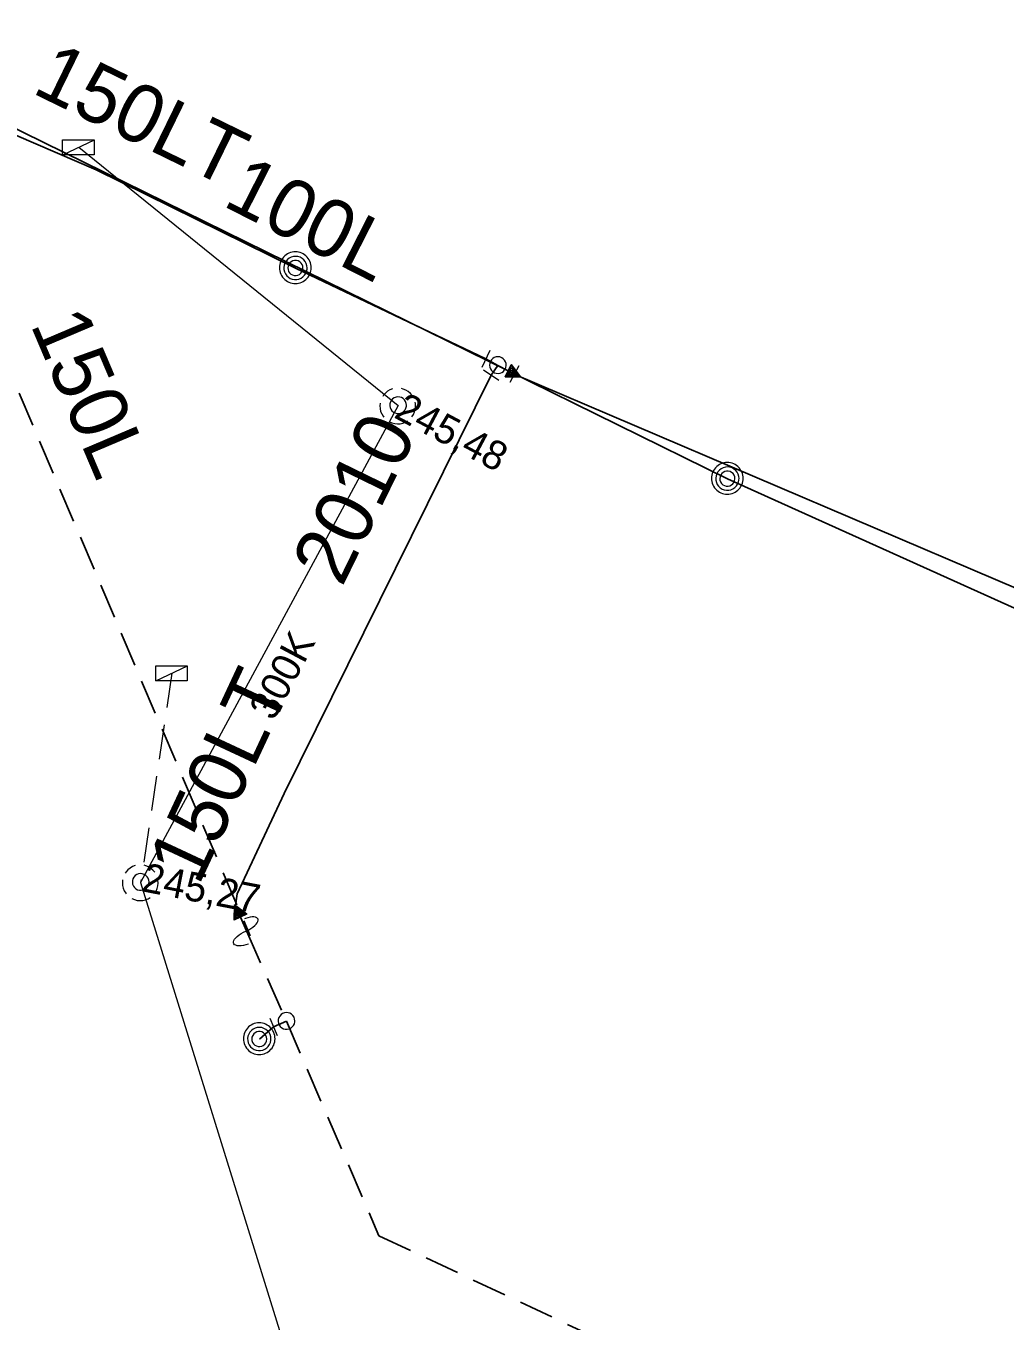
# Model space of a CAD drawing. Extents: x -735085 to -733500, y -1044153 to -1043402.
# Drawn here: x -734812.09 to -734785.04, y -1043558.45 to -1043522.67 of the extents above; entities that cross this region are included whole.
import ezdxf

# ---------------------------------------------------------------- set-up
doc = ezdxf.new("R2010")
doc.units = 0
doc.header["$LTSCALE"] = 0.32
doc.linetypes.add('MEDIUM_DASHED', pattern=[4.5, 3, -1.5])
doc.layers.add('15', color=7, linetype='Continuous')
doc.layers.add('16', color=7, linetype='Continuous')
for name, color, linetype, lineweight in [('18', 7, 'Continuous', 13), ('20', 7, 'Continuous', 13), ('49', 7, 'Continuous', 13), ('8', 7, 'Continuous', 13)]:
    doc.layers.add(name, color=color, linetype=linetype, lineweight=lineweight)

msp = doc.modelspace()

# ---------------------------------------------------------------- linework, layer by layer
at = {"layer": '18'}
for p, q in [((-734811.071, -1043526.23), (-734810.196, -1043525.818)), ((-734808.501, -1043540.76), (-734807.627, -1043540.348))]:
    msp.add_line(p, q, dxfattribs=at)
for points in [[(-734811.075, -1043525.818), (-734810.201, -1043525.818), (-734810.201, -1043526.23), (-734811.075, -1043526.23)], [(-734801.578, -1043533.149), (-734801.584, -1043533.097), (-734801.602, -1043533.047), (-734801.63, -1043533.003), (-734801.668, -1043532.966), (-734801.713, -1043532.939), (-734801.763, -1043532.923), (-734801.815, -1043532.918), (-734801.867, -1043532.925), (-734801.916, -1043532.944), (-734801.96, -1043532.974), (-734801.995, -1043533.013), (-734802.021, -1043533.058), (-734802.036, -1043533.109), (-734802.039, -1043533.161), (-734802.031, -1043533.213), (-734802.01, -1043533.261), (-734801.98, -1043533.304), (-734801.94, -1043533.339), (-734801.894, -1043533.363), (-734801.843, -1043533.377), (-734801.791, -1043533.379), (-734801.739, -1043533.369), (-734801.691, -1043533.347), (-734801.649, -1043533.315), (-734801.616, -1043533.275), (-734801.592, -1043533.228), (-734801.58, -1043533.177)], [(-734808.505, -1043540.348), (-734807.631, -1043540.348), (-734807.631, -1043540.76), (-734808.505, -1043540.76)], [(-734808.689, -1043546.319), (-734808.695, -1043546.267), (-734808.713, -1043546.217), (-734808.741, -1043546.173), (-734808.779, -1043546.136), (-734808.824, -1043546.109), (-734808.874, -1043546.093), (-734808.926, -1043546.088), (-734808.978, -1043546.095), (-734809.027, -1043546.114), (-734809.071, -1043546.144), (-734809.106, -1043546.183), (-734809.132, -1043546.228), (-734809.147, -1043546.279), (-734809.15, -1043546.331), (-734809.142, -1043546.383), (-734809.121, -1043546.431), (-734809.091, -1043546.474), (-734809.051, -1043546.509), (-734809.005, -1043546.533), (-734808.954, -1043546.547), (-734808.902, -1043546.549), (-734808.85, -1043546.539), (-734808.802, -1043546.517), (-734808.76, -1043546.485), (-734808.727, -1043546.445), (-734808.703, -1043546.398), (-734808.691, -1043546.347)]]:
    msp.add_lwpolyline(points, close=True, dxfattribs=at)
for points in [[(-734801.962, -1043532.697), (-734802.033, -1043532.725), (-734802.1, -1043532.764), (-734802.16, -1043532.812), (-734802.211, -1043532.869), (-734802.235, -1043532.903)], [(-734801.421, -1043532.88), (-734801.471, -1043532.822), (-734801.529, -1043532.772), (-734801.594, -1043532.731), (-734801.665, -1043532.702), (-734801.714, -1043532.688)], [(-734802.307, -1043533.089), (-734802.313, -1043533.166), (-734802.308, -1043533.243), (-734802.291, -1043533.318), (-734802.262, -1043533.389), (-734802.222, -1043533.455), (-734802.206, -1043533.477)], [(-734801.426, -1043533.466), (-734801.385, -1043533.401), (-734801.354, -1043533.331), (-734801.335, -1043533.256), (-734801.327, -1043533.18), (-734801.332, -1043533.103), (-734801.338, -1043533.068)], [(-734802.049, -1043533.606), (-734801.979, -1043533.637), (-734801.904, -1043533.656), (-734801.828, -1043533.663), (-734801.751, -1043533.658), (-734801.676, -1043533.641), (-734801.604, -1043533.613), (-734801.544, -1043533.578)], [(-734809.073, -1043545.867), (-734809.144, -1043545.895), (-734809.211, -1043545.934), (-734809.271, -1043545.982), (-734809.322, -1043546.039), (-734809.346, -1043546.073)], [(-734808.532, -1043546.05), (-734808.582, -1043545.992), (-734808.64, -1043545.942), (-734808.705, -1043545.901), (-734808.776, -1043545.872), (-734808.825, -1043545.858)], [(-734809.418, -1043546.259), (-734809.424, -1043546.336), (-734809.419, -1043546.413), (-734809.402, -1043546.488), (-734809.373, -1043546.559), (-734809.333, -1043546.625), (-734809.317, -1043546.647)], [(-734808.537, -1043546.636), (-734808.496, -1043546.571), (-734808.465, -1043546.501), (-734808.446, -1043546.426), (-734808.438, -1043546.35), (-734808.443, -1043546.273), (-734808.449, -1043546.238)], [(-734809.16, -1043546.776), (-734809.09, -1043546.807), (-734809.015, -1043546.826), (-734808.939, -1043546.833), (-734808.862, -1043546.828), (-734808.787, -1043546.811), (-734808.715, -1043546.783), (-734808.655, -1043546.748)]]:
    msp.add_lwpolyline(points, dxfattribs=at)
at = {"layer": '20'}
for p, q in [((-734801.809, -1043533.16), (-734808.92, -1043546.33)), ((-734801.809, -1043533.16), (-734808.92, -1043546.33)), ((-734808.92, -1043546.33), (-734802, -1043568.65)), ((-734808.92, -1043546.33), (-734802, -1043568.65))]:
    msp.add_line(p, q, dxfattribs=at)
at = {"layer": '49'}
msp.add_line((-734810.629, -1043526.02), (-734801.809, -1043533.16), dxfattribs=at)
msp.add_line((-734810.629, -1043526.02), (-734801.809, -1043533.16), dxfattribs=at)
at = {"layer": '49', "linetype": 'MEDIUM_DASHED'}
msp.add_line((-734808.059, -1043540.55), (-734808.92, -1043546.33), dxfattribs=at)
msp.add_line((-734808.059, -1043540.55), (-734808.92, -1043546.33), dxfattribs=at)
at = {"layer": '8', "linetype": 'MEDIUM_DASHED', "lineweight": 25}
for p, q in [((-734815.66, -1043524.87), (-734805.897, -1043547.809)), ((-734806, -1043547.67), (-734804.892, -1043550.168))]:
    msp.add_line(p, q, dxfattribs=at)
at = {"layer": '8'}
for p, q in [((-734799.278, -1043531.635), (-734799.501, -1043532.102)), ((-734799.023, -1043532.463), (-734799.453, -1043532.177)), ((-734798.478, -1043532.06), (-734798.72, -1043532.517)), ((-734805.351, -1043550.08), (-734805.149, -1043550.555))]:
    msp.add_line(p, q, dxfattribs=at)
at = {"layer": '8', "lineweight": 25}
for p, q in [((-734805.25, -1043550.32), (-734805.64, -1043550.66)), ((-734804.892, -1043550.168), (-734805.25, -1043550.32))]:
    msp.add_line(p, q, dxfattribs=at)
for points in [[(-734815.949, -1043522.67), (-734815.649, -1043523.18), (-734813.73, -1043525.08), (-734813.489, -1043525.21), (-734810.149, -1043526.65), (-734804.64, -1043529.36)], [(-734814.717, -1043524.389), (-734813.287, -1043525.06), (-734798.77, -1043532.2), (-734792.71, -1043535.18)], [(-734804.64, -1043529.36), (-734799.39, -1043531.87), (-734799.059, -1043532.05), (-734799.239, -1043532.32)], [(-734799.059, -1043532.05), (-734798.77, -1043532.2), (-734798.6, -1043532.29)], [(-734799.239, -1043532.32), (-734804.96, -1043543.87), (-734806.25, -1043546.65), (-734806.3, -1043546.98), (-734806.16, -1043547.29), (-734806, -1043547.67)], [(-734798.6, -1043532.29), (-734781.989, -1043539.38), (-734773.37, -1043543.03), (-734767.76, -1043545.41), (-734738.719, -1043557.66), (-734737.059, -1043558.35)], [(-734792.71, -1043535.18), (-734782.352, -1043539.852), (-734773.644, -1043543.536), (-734767.807, -1043545.587), (-734738.734, -1043557.836), (-734732.528, -1043560.258), (-734709.46, -1043569.477), (-734674.151, -1043584.087)]]:
    msp.add_lwpolyline(points, dxfattribs=at)
at = {"layer": '8'}
for points in [[(-734804.21, -1043529.349), (-734804.212, -1043529.304), (-734804.219, -1043529.259), (-734804.231, -1043529.214), (-734804.247, -1043529.172), (-734804.268, -1043529.131), (-734804.293, -1043529.092), (-734804.322, -1043529.057), (-734804.354, -1043529.024), (-734804.39, -1043528.996), (-734804.428, -1043528.971), (-734804.469, -1043528.95), (-734804.512, -1043528.933), (-734804.556, -1043528.921), (-734804.601, -1043528.914), (-734804.647, -1043528.912), (-734804.693, -1043528.914), (-734804.738, -1043528.921), (-734804.782, -1043528.933), (-734804.825, -1043528.95), (-734804.866, -1043528.971), (-734804.904, -1043528.996), (-734804.94, -1043529.024), (-734804.972, -1043529.057), (-734805.001, -1043529.092), (-734805.026, -1043529.131), (-734805.047, -1043529.172), (-734805.063, -1043529.214), (-734805.075, -1043529.259), (-734805.082, -1043529.304), (-734805.085, -1043529.35), (-734805.082, -1043529.395), (-734805.075, -1043529.44), (-734805.063, -1043529.485), (-734805.047, -1043529.527), (-734805.026, -1043529.568), (-734805.001, -1043529.607), (-734804.972, -1043529.642), (-734804.94, -1043529.675), (-734804.904, -1043529.703), (-734804.866, -1043529.728), (-734804.825, -1043529.749), (-734804.782, -1043529.766), (-734804.738, -1043529.777), (-734804.693, -1043529.785), (-734804.647, -1043529.787), (-734804.601, -1043529.785), (-734804.556, -1043529.777), (-734804.512, -1043529.766), (-734804.469, -1043529.749), (-734804.428, -1043529.728), (-734804.39, -1043529.703), (-734804.354, -1043529.675), (-734804.322, -1043529.642), (-734804.293, -1043529.607), (-734804.268, -1043529.568), (-734804.247, -1043529.527), (-734804.231, -1043529.485), (-734804.219, -1043529.44), (-734804.212, -1043529.395), (-734804.21, -1043529.35)], [(-734798.853, -1043532.367), (-734798.424, -1043532.364), (-734798.684, -1043532.023)], [(-734792.279, -1043535.168), (-734792.282, -1043535.123), (-734792.289, -1043535.078), (-734792.301, -1043535.033), (-734792.316, -1043534.991), (-734792.338, -1043534.95), (-734792.363, -1043534.911), (-734792.392, -1043534.876), (-734792.424, -1043534.843), (-734792.46, -1043534.815), (-734792.497, -1043534.79), (-734792.539, -1043534.769), (-734792.581, -1043534.752), (-734792.625, -1043534.74), (-734792.671, -1043534.733), (-734792.717, -1043534.731), (-734792.762, -1043534.733), (-734792.808, -1043534.74), (-734792.852, -1043534.752), (-734792.895, -1043534.769), (-734792.936, -1043534.79), (-734792.973, -1043534.815), (-734793.01, -1043534.843), (-734793.042, -1043534.876), (-734793.071, -1043534.911), (-734793.096, -1043534.95), (-734793.117, -1043534.991), (-734793.132, -1043535.033), (-734793.145, -1043535.078), (-734793.152, -1043535.123), (-734793.154, -1043535.169), (-734793.152, -1043535.214), (-734793.145, -1043535.259), (-734793.132, -1043535.304), (-734793.117, -1043535.346), (-734793.096, -1043535.387), (-734793.071, -1043535.426), (-734793.042, -1043535.461), (-734793.01, -1043535.494), (-734792.973, -1043535.522), (-734792.936, -1043535.547), (-734792.895, -1043535.568), (-734792.852, -1043535.585), (-734792.808, -1043535.596), (-734792.762, -1043535.604), (-734792.717, -1043535.606), (-734792.671, -1043535.604), (-734792.625, -1043535.596), (-734792.581, -1043535.585), (-734792.539, -1043535.568), (-734792.497, -1043535.547), (-734792.46, -1043535.522), (-734792.424, -1043535.494), (-734792.392, -1043535.461), (-734792.363, -1043535.426), (-734792.338, -1043535.387), (-734792.316, -1043535.346), (-734792.301, -1043535.304), (-734792.289, -1043535.259), (-734792.282, -1043535.214), (-734792.279, -1043535.169)], [(-734805.991, -1043547.208), (-734806.332, -1043546.948), (-734806.335, -1043547.377)], [(-734805.997, -1043547.668), (-734805.934, -1043547.637), (-734805.874, -1043547.602), (-734805.82, -1043547.563), (-734805.771, -1043547.525), (-734805.733, -1043547.486), (-734805.703, -1043547.447), (-734805.684, -1043547.41), (-734805.674, -1043547.378), (-734805.677, -1043547.348), (-734805.691, -1043547.324), (-734805.714, -1043547.305), (-734805.748, -1043547.292), (-734805.79, -1043547.286), (-734805.842, -1043547.286), (-734805.898, -1043547.292), (-734805.96, -1043547.305), (-734806.025, -1043547.324), (-734806.053, -1043547.335)], [(-734805.945, -1043548.037), (-734806.015, -1043548.058), (-734806.082, -1043548.072), (-734806.145, -1043548.081), (-734806.202, -1043548.082), (-734806.252, -1043548.078), (-734806.294, -1043548.068), (-734806.326, -1043548.052), (-734806.348, -1043548.03), (-734806.359, -1043548.003), (-734806.359, -1043547.971), (-734806.348, -1043547.936), (-734806.326, -1043547.899), (-734806.293, -1043547.86), (-734806.251, -1043547.821), (-734806.201, -1043547.782), (-734806.144, -1043547.743), (-734806.08, -1043547.709), (-734806.014, -1043547.676), (-734805.994, -1043547.668)], [(-734805.208, -1043550.648), (-734805.211, -1043550.603), (-734805.218, -1043550.558), (-734805.23, -1043550.513), (-734805.245, -1043550.471), (-734805.267, -1043550.43), (-734805.292, -1043550.391), (-734805.321, -1043550.356), (-734805.353, -1043550.323), (-734805.389, -1043550.295), (-734805.426, -1043550.27), (-734805.468, -1043550.249), (-734805.511, -1043550.232), (-734805.554, -1043550.22), (-734805.6, -1043550.213), (-734805.646, -1043550.211), (-734805.691, -1043550.213), (-734805.737, -1043550.22), (-734805.781, -1043550.232), (-734805.824, -1043550.249), (-734805.865, -1043550.27), (-734805.902, -1043550.295), (-734805.939, -1043550.323), (-734805.971, -1043550.356), (-734806, -1043550.391), (-734806.025, -1043550.43), (-734806.046, -1043550.471), (-734806.061, -1043550.513), (-734806.074, -1043550.558), (-734806.081, -1043550.603), (-734806.083, -1043550.649), (-734806.081, -1043550.694), (-734806.074, -1043550.739), (-734806.061, -1043550.784), (-734806.046, -1043550.826), (-734806.025, -1043550.867), (-734806, -1043550.906), (-734805.971, -1043550.941), (-734805.939, -1043550.974), (-734805.902, -1043551.002), (-734805.865, -1043551.027), (-734805.824, -1043551.048), (-734805.781, -1043551.065), (-734805.737, -1043551.076), (-734805.691, -1043551.084), (-734805.646, -1043551.086), (-734805.6, -1043551.084), (-734805.554, -1043551.076), (-734805.511, -1043551.065), (-734805.468, -1043551.048), (-734805.426, -1043551.027), (-734805.389, -1043551.002), (-734805.353, -1043550.974), (-734805.321, -1043550.941), (-734805.292, -1043550.906), (-734805.267, -1043550.867), (-734805.245, -1043550.826), (-734805.23, -1043550.784), (-734805.218, -1043550.739), (-734805.211, -1043550.694), (-734805.208, -1043550.649)]]:
    msp.add_lwpolyline(points, dxfattribs=at)
for points in [[(-734804.323, -1043529.357), (-734804.329, -1043529.296), (-734804.347, -1043529.236), (-734804.376, -1043529.181), (-734804.415, -1043529.133), (-734804.462, -1043529.093), (-734804.516, -1043529.063), (-734804.575, -1043529.043), (-734804.637, -1043529.036), (-734804.699, -1043529.04), (-734804.759, -1043529.056), (-734804.814, -1043529.084), (-734804.864, -1043529.121), (-734804.905, -1043529.168), (-734804.937, -1043529.221), (-734804.957, -1043529.28), (-734804.967, -1043529.341), (-734804.964, -1043529.403), (-734804.949, -1043529.463), (-734804.923, -1043529.52), (-734804.887, -1043529.57), (-734804.841, -1043529.613), (-734804.789, -1043529.645), (-734804.731, -1043529.668), (-734804.67, -1043529.678), (-734804.608, -1043529.677), (-734804.547, -1043529.664), (-734804.49, -1043529.639), (-734804.439, -1043529.604), (-734804.395, -1043529.56), (-734804.361, -1043529.508), (-734804.337, -1043529.451), (-734804.325, -1043529.39)], [(-734804.437, -1043529.357), (-734804.443, -1043529.308), (-734804.46, -1043529.261), (-734804.488, -1043529.22), (-734804.526, -1043529.187), (-734804.57, -1043529.163), (-734804.618, -1043529.151), (-734804.668, -1043529.15), (-734804.716, -1043529.162), (-734804.761, -1043529.184), (-734804.799, -1043529.217), (-734804.828, -1043529.257), (-734804.847, -1043529.304), (-734804.854, -1043529.353), (-734804.849, -1043529.403), (-734804.832, -1043529.45), (-734804.805, -1043529.492), (-734804.768, -1043529.526), (-734804.725, -1043529.55), (-734804.677, -1043529.564), (-734804.627, -1043529.565), (-734804.578, -1043529.555), (-734804.533, -1043529.533), (-734804.494, -1043529.501), (-734804.464, -1043529.462), (-734804.445, -1043529.416), (-734804.437, -1043529.366)], [(-734798.851, -1043532.151), (-734798.831, -1043532.102), (-734798.823, -1043532.05), (-734798.826, -1043531.998), (-734798.842, -1043531.947), (-734798.869, -1043531.902), (-734798.905, -1043531.864), (-734798.948, -1043531.835), (-734798.997, -1043531.816), (-734799.049, -1043531.809), (-734799.102, -1043531.814), (-734799.152, -1043531.832), (-734799.196, -1043531.859), (-734799.234, -1043531.896), (-734799.261, -1043531.941), (-734799.279, -1043531.99), (-734799.284, -1043532.042), (-734799.278, -1043532.094), (-734799.259, -1043532.144), (-734799.231, -1043532.187), (-734799.192, -1043532.224), (-734799.148, -1043532.251), (-734799.097, -1043532.267), (-734799.045, -1043532.271), (-734798.992, -1043532.263), (-734798.944, -1043532.243), (-734798.901, -1043532.214), (-734798.866, -1043532.175)], [(-734798.853, -1043532.367), (-734798.684, -1043532.023), (-734798.424, -1043532.364)], [(-734798.812, -1043532.336), (-734798.683, -1043532.074), (-734798.479, -1043532.337)], [(-734798.774, -1043532.311), (-734798.679, -1043532.118), (-734798.534, -1043532.31)], [(-734798.68, -1043532.171), (-734798.583, -1043532.286), (-734798.733, -1043532.28)], [(-734798.676, -1043532.215), (-734798.637, -1043532.259), (-734798.696, -1043532.256)], [(-734792.392, -1043535.176), (-734792.399, -1043535.115), (-734792.417, -1043535.055), (-734792.446, -1043535), (-734792.485, -1043534.952), (-734792.532, -1043534.912), (-734792.586, -1043534.882), (-734792.645, -1043534.862), (-734792.706, -1043534.855), (-734792.769, -1043534.859), (-734792.828, -1043534.875), (-734792.884, -1043534.903), (-734792.934, -1043534.94), (-734792.975, -1043534.987), (-734793.007, -1043535.04), (-734793.027, -1043535.099), (-734793.037, -1043535.16), (-734793.034, -1043535.222), (-734793.019, -1043535.282), (-734792.993, -1043535.339), (-734792.956, -1043535.389), (-734792.911, -1043535.432), (-734792.858, -1043535.464), (-734792.801, -1043535.487), (-734792.74, -1043535.497), (-734792.678, -1043535.496), (-734792.617, -1043535.483), (-734792.559, -1043535.458), (-734792.509, -1043535.423), (-734792.465, -1043535.379), (-734792.431, -1043535.327), (-734792.407, -1043535.27), (-734792.395, -1043535.209)], [(-734792.507, -1043535.176), (-734792.512, -1043535.127), (-734792.529, -1043535.08), (-734792.558, -1043535.039), (-734792.596, -1043535.006), (-734792.64, -1043534.982), (-734792.688, -1043534.97), (-734792.738, -1043534.969), (-734792.786, -1043534.981), (-734792.831, -1043535.003), (-734792.869, -1043535.036), (-734792.897, -1043535.076), (-734792.917, -1043535.123), (-734792.924, -1043535.172), (-734792.919, -1043535.222), (-734792.902, -1043535.269), (-734792.875, -1043535.311), (-734792.838, -1043535.345), (-734792.794, -1043535.369), (-734792.747, -1043535.383), (-734792.696, -1043535.384), (-734792.647, -1043535.374), (-734792.603, -1043535.352), (-734792.564, -1043535.32), (-734792.534, -1043535.281), (-734792.515, -1043535.235), (-734792.507, -1043535.185)], [(-734805.991, -1043547.208), (-734806.335, -1043547.377), (-734806.332, -1043546.948)], [(-734806.042, -1043547.207), (-734806.304, -1043547.336), (-734806.305, -1043547.003)], [(-734806.087, -1043547.204), (-734806.28, -1043547.299), (-734806.278, -1043547.058)], [(-734806.248, -1043547.257), (-734806.254, -1043547.107), (-734806.139, -1043547.204)], [(-734806.224, -1043547.22), (-734806.227, -1043547.161), (-734806.183, -1043547.2)], [(-734804.661, -1043550.157), (-734804.667, -1043550.105), (-734804.684, -1043550.055), (-734804.713, -1043550.011), (-734804.751, -1043549.974), (-734804.796, -1043549.947), (-734804.846, -1043549.931), (-734804.898, -1043549.926), (-734804.95, -1043549.933), (-734804.999, -1043549.952), (-734805.043, -1043549.982), (-734805.078, -1043550.021), (-734805.104, -1043550.066), (-734805.119, -1043550.117), (-734805.122, -1043550.169), (-734805.114, -1043550.221), (-734805.093, -1043550.269), (-734805.063, -1043550.312), (-734805.023, -1043550.347), (-734804.977, -1043550.371), (-734804.926, -1043550.385), (-734804.874, -1043550.387), (-734804.822, -1043550.377), (-734804.774, -1043550.355), (-734804.732, -1043550.323), (-734804.699, -1043550.283), (-734804.675, -1043550.236), (-734804.663, -1043550.185)], [(-734805.321, -1043550.656), (-734805.328, -1043550.595), (-734805.346, -1043550.535), (-734805.375, -1043550.48), (-734805.414, -1043550.432), (-734805.461, -1043550.392), (-734805.515, -1043550.362), (-734805.574, -1043550.342), (-734805.636, -1043550.335), (-734805.698, -1043550.339), (-734805.757, -1043550.355), (-734805.813, -1043550.383), (-734805.863, -1043550.42), (-734805.904, -1043550.467), (-734805.936, -1043550.52), (-734805.956, -1043550.579), (-734805.966, -1043550.64), (-734805.963, -1043550.702), (-734805.948, -1043550.762), (-734805.922, -1043550.819), (-734805.886, -1043550.869), (-734805.84, -1043550.912), (-734805.788, -1043550.944), (-734805.73, -1043550.967), (-734805.669, -1043550.977), (-734805.607, -1043550.976), (-734805.546, -1043550.963), (-734805.489, -1043550.938), (-734805.438, -1043550.903), (-734805.394, -1043550.859), (-734805.36, -1043550.807), (-734805.336, -1043550.75), (-734805.324, -1043550.689)], [(-734805.436, -1043550.656), (-734805.441, -1043550.607), (-734805.458, -1043550.56), (-734805.487, -1043550.519), (-734805.525, -1043550.486), (-734805.569, -1043550.462), (-734805.617, -1043550.45), (-734805.667, -1043550.449), (-734805.715, -1043550.461), (-734805.76, -1043550.483), (-734805.798, -1043550.516), (-734805.826, -1043550.556), (-734805.846, -1043550.603), (-734805.853, -1043550.652), (-734805.848, -1043550.702), (-734805.831, -1043550.749), (-734805.804, -1043550.791), (-734805.767, -1043550.825), (-734805.723, -1043550.849), (-734805.676, -1043550.863), (-734805.625, -1043550.864), (-734805.576, -1043550.854), (-734805.532, -1043550.832), (-734805.493, -1043550.8), (-734805.463, -1043550.761), (-734805.444, -1043550.715), (-734805.436, -1043550.665)]]:
    msp.add_lwpolyline(points, close=True, dxfattribs=at)
at = {"layer": '8', "linetype": 'MEDIUM_DASHED', "lineweight": 25}
msp.add_lwpolyline([(-734804.892, -1043550.168), (-734802.34, -1043556.09), (-734769.804, -1043571.373), (-734765.02, -1043573.62)], dxfattribs=at)

# ---------------------------------------------------------------- texts
at = {"layer": '15'}
for s, rotation, p in [('150LT ', 334, (-734811.958, -1043524.505)), ('100L', 333, (-734806.692, -1043527.619)), ('150L', 293, (-734811.976, -1043530.911)), ('2010', 64, (-734803.359, -1043538.196)), ('150LT ', 65, (-734807.32, -1043546.451))]:
    msp.add_text(s, height=1.6, rotation=rotation, dxfattribs=at).set_placement(p)
at = {"layer": '16'}
for s, rotation, p in [('245,48', 332, (-734801.955, -1043533.474)), ('300K', 62, (-734805.25, -1043541.894)), ('245,27', 349, (-734808.924, -1043546.569))]:
    msp.add_text(s, height=0.8, rotation=rotation, dxfattribs=at).set_placement(p)

doc.saveas('drawing.dxf')
